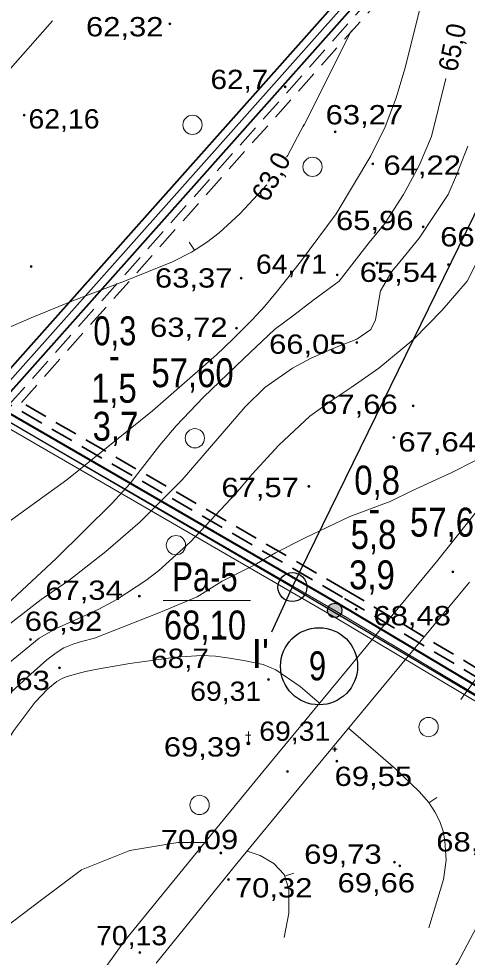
# Model space of a CAD drawing. Extents: x 628176 to 629009, y 6439913 to 6440496.
# Drawn here: x 628239.5 to 628286, y 6440164.9 to 6440262.2 of the extents above; entities that cross this region are included whole.
import ezdxf
from ezdxf.enums import TextEntityAlignment as Align

# ---------------------------------------------------------------- set-up
doc = ezdxf.new("R2010")
doc.units = 0
doc.header["$LTSCALE"] = 0.8
doc.linetypes.add('MEDIUM_DASHED', pattern=[4.5, 3, -1.5])
for name, color, linetype, lineweight in [('1', 7, 'Continuous', 13), ('10', 7, 'Continuous', 25), ('11', 7, 'Continuous', 13), ('12', 7, 'Continuous', 13), ('14', 7, 'Continuous', 25), ('16', 7, 'Continuous', 13), ('20', 7, 'Continuous', 40), ('21', 7, 'MEDIUM_DASHED', 35), ('3', 7, 'Continuous', 13), ('6', 7, 'Continuous', 13)]:
    doc.layers.add(name, color=color, linetype=linetype, lineweight=lineweight)

msp = doc.modelspace()

# ---------------------------------------------------------------- hatches: boundary and pattern name
at = {"layer": '1'}
for points in [[(628255.2647, 6440261.6686, 1), (628255.0647, 6440261.6686, 1)], [(628267.2291, 6440255.1461, 1), (628267.0291, 6440255.1461, 1)], [(628240.1608, 6440252.2082, 1), (628239.9608, 6440252.2082, 1)], [(628272.4082, 6440250.4909, 1), (628272.2082, 6440250.4909, 1)], [(628276.2913, 6440247.1534, 1), (628276.0913, 6440247.1534, 1)], [(628281.5118, 6440240.6503, 1), (628281.3118, 6440240.6503, 1)], [(628240.8777, 6440236.5407, 1), (628240.6777, 6440236.5407, 1)], [(628276.7601, 6440236.8922, 1), (628276.5601, 6440236.8922, 1)], [(628284.1512, 6440236.7167, 1), (628283.9512, 6440236.7167, 1)], [(628272.622, 6440235.6506, 1), (628272.422, 6440235.6506, 1)], [(628262.6527, 6440235.3101, 1), (628262.4527, 6440235.3101, 1)], [(628262.1695, 6440230.1458, 1), (628261.9695, 6440230.1458, 1)], [(628274.6539, 6440228.6642, 1), (628274.4539, 6440228.6642, 1)], [(628280.4766, 6440222.0724, 1), (628280.2766, 6440222.0724, 1)], [(628278.4805, 6440218.804, 1), (628278.2805, 6440218.804, 1)], [(628269.6698, 6440213.7458, 1), (628269.4698, 6440213.7458, 1)], [(628284.611, 6440204.8725, 1), (628284.411, 6440204.8725, 1)], [(628252.0985, 6440202.3686, 1), (628251.8985, 6440202.3686, 1)], [(628274.5677, 6440201.0063, 1), (628274.3677, 6440201.0063, 1)], [(628240.8288, 6440197.8739, 1), (628240.6288, 6440197.8739, 1)], [(628260.5404, 6440198.174, 1), (628260.3404, 6440198.174, 1)], [(628243.8207, 6440194.9384, 1), (628243.6207, 6440194.9384, 1)], [(628265.4916, 6440193.7221, 1), (628265.2916, 6440193.7221, 1)], [(628263.4487, 6440187.1109, 1), (628263.1487, 6440187.1109, 1)], [(628272.3749, 6440186.4887, 1), (628272.1749, 6440186.4887, 1)], [(628272.5676, 6440185.2709, 1), (628272.3676, 6440185.2709, 1)], [(628267.4477, 6440184.1775, 1), (628267.2477, 6440184.1775, 1)], [(628260.5472, 6440175.7421, 1), (628260.3472, 6440175.7421, 1)], [(628278.5492, 6440174.7968, 1), (628278.3492, 6440174.7968, 1)], [(628279.089, 6440174.4233, 1), (628278.889, 6440174.4233, 1)], [(628261.3278, 6440173.0015, 1), (628261.1278, 6440173.0015, 1)], [(628252.162, 6440165.4311, 1), (628251.962, 6440165.4311, 1)]]:
    msp.add_hatch(color=256, dxfattribs=at).paths.add_polyline_path(points)
at = {"layer": '10'}
msp.add_hatch(color=256, dxfattribs=at).paths.add_polyline_path([(628273, 6440200.89, 1), (628271.5, 6440200.89, 1)])

# ---------------------------------------------------------------- linework, layer by layer
at = {"layer": '1'}
for p, q in [((628282.81, 6440205.93), (628294.9, 6440221.2)), ((628265.59, 6440185.14), (628282.81, 6440205.93)), ((628269.01, 6440183.06), (628286.21, 6440203.81)), ((628263.3, 6440187.26), (628263.3, 6440188.33)), ((628263.57, 6440187.96), (628263.02, 6440187.96)), ((628272.27, 6440186.49), (628272.02, 6440186.49)), ((628272.27, 6440186.49), (628272.27, 6440186.74)), ((628272.27, 6440186.49), (628272.52, 6440186.49)), ((628272.27, 6440186.49), (628272.27, 6440186.24)), ((628258.78, 6440176.84), (628265.59, 6440185.14)), ((628262.12, 6440174.64), (628269.01, 6440183.06)), ((628250.4, 6440166.54), (628258.78, 6440176.84)), ((628253.73, 6440164.32), (628262.12, 6440174.64)), ((628234.54, 6440144.61), (628250.4, 6440166.54))]:
    msp.add_line(p, q, dxfattribs=at)
for centre, radius in [((628255.1647, 6440261.6686), 0.1), ((628267.1291, 6440255.1461), 0.1), ((628240.0608, 6440252.2082), 0.1), ((628257.5094, 6440251.2061), 1), ((628272.3082, 6440250.4909), 0.1), ((628269.9521, 6440246.8566), 1), ((628276.1913, 6440247.1534), 0.1), ((628281.4118, 6440240.6503), 0.1), ((628240.7777, 6440236.5407), 0.1), ((628276.6601, 6440236.8922), 0.1), ((628284.0512, 6440236.7167), 0.1), ((628272.522, 6440235.6506), 0.1), ((628262.5527, 6440235.3101), 0.1), ((628262.0695, 6440230.1458), 0.1), ((628274.5539, 6440228.6642), 0.1), ((628280.3766, 6440222.0724), 0.1), ((628257.7551, 6440218.7287), 1), ((628278.3805, 6440218.804), 0.1), ((628269.5698, 6440213.7458), 0.1), ((628255.7963, 6440207.6439), 1), ((628284.511, 6440204.8725), 0.1), ((628251.9985, 6440202.3686), 0.1), ((628274.4677, 6440201.0063), 0.1), ((628240.7288, 6440197.8739), 0.1), ((628260.4404, 6440198.174), 0.1), ((628243.7207, 6440194.9384), 0.1), ((628265.3916, 6440193.7221), 0.1), ((628281.9826, 6440188.7995), 1), ((628263.2987, 6440187.1109), 0.15), ((628272.2749, 6440186.4887), 0.1), ((628272.4676, 6440185.2709), 0.1), ((628267.3477, 6440184.1775), 0.1), ((628258.2436, 6440180.7234), 1), ((628260.4472, 6440175.7421), 0.1), ((628278.4492, 6440174.7968), 0.1), ((628278.989, 6440174.4233), 0.1), ((628261.2278, 6440173.0015), 0.1), ((628252.062, 6440165.4311), 0.1)]:
    msp.add_circle(centre, radius, dxfattribs=at)
at = {"layer": '10'}
for centre, radius in [((628272.25, 6440200.89), 0.75), ((628270.6303, 6440195.0966), 4)]:
    msp.add_circle(centre, radius, dxfattribs=at)
at = {"layer": '11'}
msp.add_lwpolyline([(628497.5, 6440118.54), (628474.19, 6440080.39), (628272.25, 6440200.89), (628236.02, 6440221.83), (628393.19, 6440398.39)], dxfattribs=at)
at = {"layer": '12'}
msp.add_line((628254.47, 6440201.9), (628263.51, 6440201.9), dxfattribs=at)
at = {"layer": '12', "lineweight": 25}
msp.add_circle((628267.8621, 6440203.2978), 1.5, dxfattribs=at)
at = {"layer": '14'}
for p, q in [((628326.62, 6440323.6), (628267.86, 6440203.3)), ((628267.86, 6440203.3), (628265.69, 6440198.63))]:
    msp.add_line(p, q, dxfattribs=at)
for points in [[(628267.86, 6440203.3), (628236.02, 6440221.83), (628232.27, 6440224.02)], [(628267.86, 6440203.3), (628311.23, 6440177.63), (628327.53, 6440167.88), (628373.06, 6440140.73), (628474.19, 6440080.39), (628476.16, 6440079.17)]]:
    msp.add_lwpolyline(points, dxfattribs=at)
at = {"layer": '16'}
msp.add_spline([(628330.97, 6440258.09), (628324.85, 6440247.37), (628318.95, 6440237.06), (628309.38, 6440220.86), (628299.81, 6440210.06), (628285.32, 6440191.65)], degree=3, dxfattribs=at)
at = {"layer": '20'}
msp.add_line((628235.32, 6440222.24), (628409.42, 6440417.82), dxfattribs=at)
at = {"layer": '21', "linetype": 'Continuous', "lineweight": 40}
msp.add_lwpolyline([(628320.39, 6440173.09), (628272.66, 6440201.58), (628237.27, 6440222.03), (628393.6, 6440397.65)], dxfattribs=at)
at = {"layer": '21'}
for points in [[(628321.72, 6440173.24), (628273.06, 6440202.27), (628238.52, 6440222.23), (628394.01, 6440396.91)], [(628321.66, 6440174.2), (628273.47, 6440202.96), (628239.77, 6440222.44), (628394.43, 6440396.17)]]:
    msp.add_lwpolyline(points, dxfattribs=at)
at = {"layer": '3'}
for p, q in [((628268.99, 6440251), (628274, 6440261)), ((628282.27, 6440250), (628283.77, 6440256)), ((628277.5, 6440251), (628278.61, 6440254)), ((628267.35, 6440248), (628269.08, 6440251.29)), ((628277.5, 6440251), (628276, 6440248)), ((628282.27, 6440250), (628281, 6440247)), ((628286.06, 6440249), (628284.87, 6440246)), ((628267.35, 6440248), (628267.25, 6440247.86)), ((628276, 6440248), (628272.39, 6440242)), ((628262.41, 6440242), (628265.21, 6440245)), ((628260.27, 6440240), (628262.41, 6440242)), ((628272.39, 6440242), (628268.71, 6440237)), ((628260.27, 6440240), (628258.95, 6440239)), ((628257.18, 6440239.05), (628257.72, 6440238.21)), ((628258.95, 6440239), (628257.39, 6440238)), ((628275.81, 6440239), (628272.71, 6440235)), ((628279, 6440237), (628281, 6440239.48)), ((628257.39, 6440238), (628255.44, 6440237)), ((628255.44, 6440237), (628250.45, 6440235)), ((628279, 6440237), (628278.18, 6440236)), ((628250.45, 6440235), (628245.18, 6440233)), ((628272.71, 6440235), (628270, 6440233)), ((628270, 6440233), (628268, 6440231.49)), ((628265, 6440232.43), (628263.69, 6440231)), ((628263.69, 6440231), (628261.69, 6440229)), ((628268, 6440231.49), (628266, 6440230)), ((628266, 6440230), (628262.82, 6440227)), ((628267.87, 6440226), (628265.01, 6440224)), ((628262.97, 6440222), (628265.01, 6440224)), ((628255.83, 6440220), (628254.12, 6440218)), ((628254.12, 6440218), (628251, 6440214)), ((628251, 6440214), (628249.17, 6440212)), ((628244.68, 6440204), (628248.51, 6440207)), ((628249.66, 6440202), (628252.69, 6440204)), ((628247.79, 6440201), (628249.66, 6440202)), ((628245.64, 6440200), (628247.79, 6440201)), ((628243.37, 6440199), (628245.64, 6440200)), ((628241.6, 6440198), (628243.37, 6440199)), ((628241.6, 6440198), (628220.23, 6440180.45)), ((628242.42, 6440195.77), (628240.44, 6440194)), ((628242.42, 6440195.77), (628243.39, 6440196.5)), ((628258.49, 6440196.21), (628256.3, 6440196.07)), ((628235.42, 6440189.43), (628240.44, 6440194)), ((628244, 6440193.83), (628244.42, 6440194)), ((628244.42, 6440194), (628245, 6440194.19)), ((628268.68, 6440193), (628270.68, 6440191.28)), ((628273.68, 6440188.69), (628278.57, 6440184.48)), ((628282.85, 6440181.49), (628282.01, 6440180.94)), ((628283.15, 6440179), (628283.48, 6440178)), ((628283.48, 6440178), (628283.68, 6440177)), ((628283.81, 6440175), (628283.68, 6440177)), ((628268, 6440173.66), (628267.05, 6440173.35))]:
    msp.add_line(p, q, dxfattribs=at)
for points in [[(628278.61, 6440254), (628279.52, 6440257), (628285, 6440279)], [(628224, 6440243), (628236.8, 6440255), (628243, 6440262)], [(628291.5, 6440248), (628290, 6440243), (628286, 6440235), (628283.4, 6440232)], [(628275.81, 6440239), (628277.44, 6440241), (628279.39, 6440244), (628281, 6440247)], [(628284.87, 6440246), (628284, 6440244), (628282.57, 6440241.8), (628281, 6440239.48)], [(628268.71, 6440237), (628266.33, 6440234), (628265, 6440232.43)], [(628267.87, 6440226), (628269.75, 6440227), (628272, 6440228), (628274.55, 6440229), (628276, 6440230), (628276.49, 6440231), (628277, 6440234), (628278.18, 6440236)], [(628245.18, 6440233), (628240.78, 6440231.22), (628233.35, 6440228), (628227.28, 6440225), (628222.14, 6440222)], [(628263.71, 6440215), (628266.47, 6440218), (628269.67, 6440221), (628272, 6440222.68), (628273.97, 6440224), (628276.84, 6440226), (628280.46, 6440229), (628283.4, 6440232)], [(628261.69, 6440229), (628260, 6440227.39), (628253.37, 6440221.56), (628244.49, 6440214.43), (628230, 6440204)], [(628262.82, 6440227), (628258.66, 6440223), (628255.83, 6440220)], [(628247.36, 6440198), (628250.26, 6440199.16), (628254.18, 6440200.71), (628258.01, 6440202.29), (628260.57, 6440203.93), (628263.92, 6440205.56), (628266.12, 6440206.84), (628269.18, 6440208.41), (628273.81, 6440210.62), (628278, 6440212.18), (628280.26, 6440213.27), (628284.41, 6440215.17), (628289.01, 6440217.52), (628292.3, 6440220.03), (628294, 6440221.9)], [(628248.51, 6440207), (628252.1, 6440210.08), (628256.44, 6440214.43), (628262.97, 6440222)], [(628257.29, 6440208), (628261.99, 6440213), (628263.71, 6440215)], [(628249.17, 6440212), (628243.37, 6440206.27), (628238.83, 6440202), (628236.1, 6440199.6), (628232.65, 6440197), (628220, 6440189)], [(628252.69, 6440204), (628253.98, 6440205), (628257.29, 6440208)], [(628244.68, 6440204), (628241.81, 6440202), (628237, 6440198.3), (628226, 6440190)], [(628247.36, 6440198), (628246, 6440197.67), (628245.21, 6440197.41), (628244.18, 6440197), (628243.39, 6440196.5)], [(628251, 6440195.38), (628255.52, 6440196), (628256.3, 6440196.07)], [(628258.49, 6440196.21), (628259.89, 6440196.15), (628261.36, 6440195.94), (628263, 6440195.67), (628264.84, 6440195.28), (628266.16, 6440194.74), (628268.68, 6440193)], [(628251, 6440195.38), (628247.62, 6440194.8), (628246.43, 6440194.57), (628245, 6440194.19)], [(628244, 6440193.83), (628243.43, 6440193.51), (628242.5, 6440192.75), (628241.17, 6440191.34), (628239, 6440188.44), (628235, 6440182), (628232.14, 6440178), (628227, 6440172)], [(628291, 6440186), (628291, 6440183), (628290.67, 6440179), (628290.19, 6440176), (628289.67, 6440174), (628288.49, 6440171), (628285, 6440164.4), (628277, 6440153), (628270.83, 6440142.75)], [(628283.15, 6440179), (628282.64, 6440180), (628282, 6440180.96), (628281, 6440182.11), (628278.57, 6440184.48)], [(628258.78, 6440176.84), (628256, 6440176.84), (628251, 6440176), (628246, 6440174), (628242, 6440171), (628236.67, 6440167)], [(628263.19, 6440175.95), (628264.53, 6440175.5), (628265.94, 6440174.64), (628267, 6440173.51), (628267.49, 6440172), (628267.49, 6440169.51), (628267, 6440167)], [(628282, 6440168), (628283.54, 6440173), (628283.81, 6440175)]]:
    msp.add_lwpolyline(points, dxfattribs=at)
at = {"layer": '6'}
msp.add_lwpolyline([(628473.77, 6440079.94), (628271.95, 6440200.37), (628235.6, 6440221.38)], dxfattribs=at)

# ---------------------------------------------------------------- texts
at = {"layer": '1'}
for s, width, p in [('62,32', 1.2, (628246.47, 6440260.38)), ('62,7', 1.15, (628259.38, 6440254.92)), ('63,27', 1.2, (628271.31, 6440251.26)), ('62,16', 1.1, (628240.51, 6440250.83)), ('64,22', 1.2, (628277.31, 6440246.03)), ('65,96', 1.2, (628272.39, 6440240.3)), ('66,68', 1.2, (628283.19, 6440238.61)), ('64,71', 1.1, (628264.09, 6440235.77)), ('65,54', 1.2, (628274.85, 6440234.93)), ('63,37', 1.2, (628253.62, 6440234.34)), ('63,72', 1.2, (628253.11, 6440229.23)), ('66,05', 1.2, (628265.45, 6440227.48)), ('67,66', 1.2, (628270.75, 6440221.25)), ('67,64', 1.2, (628278.86, 6440217.35)), ('67,57', 1.2, (628260.51, 6440212.63)), ('67,34', 1.2, (628242.25, 6440201.98)), ('66,92', 1.2, (628240.12, 6440198.76)), ('68,48', 1.2, (628276.27, 6440199.34)), ('68,7', 1.15, (628253.23, 6440194.92)), ('68,63', 1.2, (628234.69, 6440192.63)), ('69,31', 1.1, (628257.27, 6440191.51)), ('69,31', 1.1, (628264.43, 6440187.37)), ('69,39', 1.2, (628254.54, 6440185.74)), ('69,55', 1.2, (628272.24, 6440182.69)), ('70,09', 1.2, (628254.22, 6440176.14)), ('68,67', 1.2, (628282.78, 6440175.9)), ('69,73', 1.2, (628269.09, 6440174.63)), ('69,66', 1.2, (628272.55, 6440171.66)), ('70,32', 1.2, (628261.91, 6440171.14)), ('70,13', 1.1, (628247.52, 6440166.18))]:
    msp.add_text(s, height=2, dxfattribs=dict(at, width=width)).set_placement(p)
at = {"layer": '10', "width": 0.8}
msp.add_text('9', height=3, dxfattribs=at).set_placement((628270.47, 6440193.64), align=Align.CENTER)
at = {"layer": '11'}
for s, width, p in [('0,3', 0.8, (628249.46, 6440228.36)), ('0,8', 0.85, (628276.65, 6440212.89))]:
    msp.add_text(s, height=3, dxfattribs=dict(at, width=width)).set_placement(p, align=Align.CENTER)
at = {"layer": '12'}
for s, width, p in [('-', 0.85, (628249.41, 6440225.83)), ('57,60', 0.85, (628257.515, 6440224.02)), ('1,5', 0.85, (628249.36, 6440222.41)), ('3,7', 0.85, (628249.53, 6440218.47)), ('57,60', 0.85, (628284.325, 6440208.53)), ('-', 0.9, (628276.365, 6440209.96)), ('5,8', 0.85, (628276.275, 6440207.25)), ('Pa-5', 0.8, (628258.805, 6440202.87)), ('3,9', 0.85, (628276.115, 6440203.07)), ('68,10', 0.85, (628258.805, 6440197.87))]:
    msp.add_text(s, height=3, dxfattribs=dict(at, width=width)).set_placement(p, align=Align.CENTER)
at = {"layer": '14', "width": 0.95}
msp.add_text("I'", height=3, dxfattribs=at).set_placement((628264.545, 6440194.93), align=Align.CENTER)
at = {"layer": '3', "width": 0.95}
msp.add_text('65,0', height=2, rotation=78.435, dxfattribs=at).set_placement((628284.92, 6440256.62))
at = {"layer": '3'}
msp.add_text('63,0', height=2, rotation=61.273, dxfattribs=at).set_placement((628265.28, 6440243.08))

doc.saveas('drawing.dxf')
